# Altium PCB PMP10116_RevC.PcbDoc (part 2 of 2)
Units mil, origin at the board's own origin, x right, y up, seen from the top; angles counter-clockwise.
Board outline 9441.58 x 3500 mil, 2 copper layers (Top Layer, Bottom Layer), stack 62 mil thick; 153 components, 82 nets, 354 pads, 48 vias.
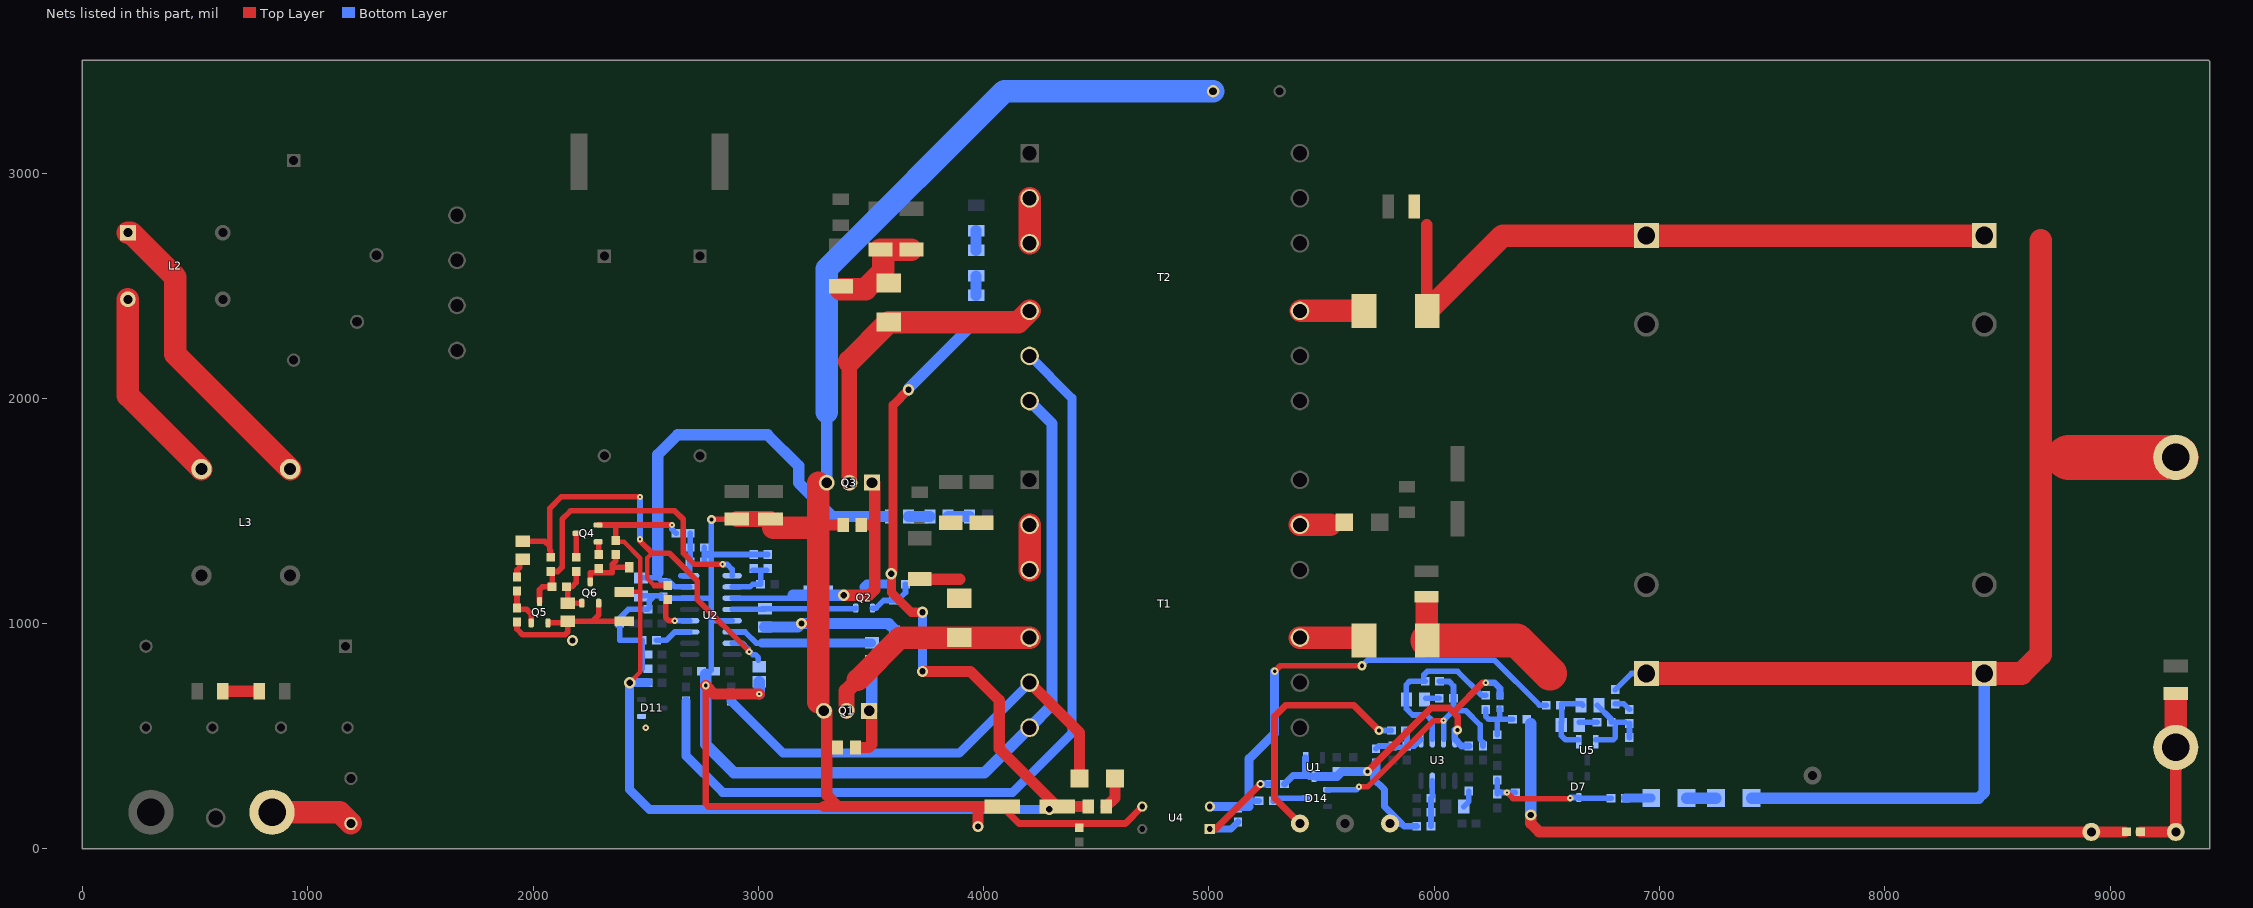
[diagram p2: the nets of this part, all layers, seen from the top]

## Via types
v1: diameter 50, hole 28, Top Layer to Bottom Layer, 21 vias
v2: diameter 28, hole 10, Top Layer to Bottom Layer, 16 vias
v3: diameter 40, hole 18, Top Layer to Bottom Layer, 8 vias
v4: diameter 34, hole 16, Top Layer to Bottom Layer, 3 vias

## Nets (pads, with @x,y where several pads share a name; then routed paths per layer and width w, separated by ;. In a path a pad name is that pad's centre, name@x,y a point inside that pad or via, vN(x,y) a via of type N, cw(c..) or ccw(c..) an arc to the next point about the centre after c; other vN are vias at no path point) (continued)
NetC26_1: C26.1 Q2.2 U2.12 | length 561.8
  Bottom Layer w25: U2.12@2884,1063.16 2939.51,1063.16 C26.1@3029.08,1063.16 ; C26.1@3016.58,1065.66 3428.91,1065.66 Q2.2@3432.05,1068.8
NetC27_2: C27.2 R35.1 | length 77.8
  Bottom Layer w25: C27.2@6131.58,188.16 6154.08,210.66 R35.1@6154.08,256.66
NetC29_1: C29.1 R34.1 R40.2 U2.8 | length 223.9
  Bottom Layer w25: U2.8@2655.55,1213.16 U2.8@2695.02,1213.16 C29.1@2695.02,1273.1 ; C29.1@2697.58,1275.66 R40.2@2697.58,1338.16 ; R40.2@2698.07,1338.65 R34.1@2698.07,1400.66
NetC30_1: C30.1 D7.3 R18.1 R38.1 R39.1 | length 614
  Top Layer w25: v2(6322.58,250.66) 6349.85,223.39 6601.81,223.39 v2(6604.08,225.66)
  Bottom Layer w25: R38.1@6279.08,244.65 C30.1@6279.08,306.66 ; R38.1@6285.08,250.66 v2(6322.58,250.66) R39.1@6360.08,250.66 ; v2(6604.08,225.66) 6606.83,228.41 D7.3@6641.58,228.41 6644.33,225.66 R18.1@6785.08,225.66
NetC31_1: C31.1 R41.1 R43.2 U2.10 | length 253.1
  Bottom Layer w25: U2.10@2884,1163.16 2963.16,1163.16 2975.66,1175.66 R41.1@3010.08,1175.66 3010.08,1235.04 ; C31.1@2975,1237.5 R43.2@3037.5,1237.5
NetC32_1: C32.1 R42.1 R45.2 U3.3 | length 204
  Bottom Layer w25: R42.1@5985.57,100.66 C32.1@5985.57,163.16 R45.2@5985.57,225.66 5991.58,231.66 U3.3@5991.58,302.14
NetC33_2: C33.2 R55.2 | length 88.9
  Top Layer w25: R55.2@1929.08,1207.15 1929.08,1238.16 1941.58,1250.66 1941.58,1273.16 C33.2@1954.08,1285.66
NetC35_1: C35.1 C42.1 D14.1 R59.2 U3.7 | length 1198.6
  Top Layer w25: v2(5666.58,275.66) 5704.08,275.66 5998.07,569.66 v2(6041.58,569.66)
  Bottom Layer w25: D14.1@5526.32,263.06 5653.98,263.06 v2(5666.58,275.66) ; C35.1@6023.07,744.66 6024.65,743.08 6066.58,743.08 6085.57,724.08 R59.2@6085.57,669.66 6085.57,613.65 ; U3.7@6041.58,487.17 v2(6041.58,569.66) ; v2@6050.83,578.91 6085.57,613.65 ; C42.1@6216.58,457.15 6216.58,473.14 6204.08,485.64 6204.08,550.66 6141.08,613.65 6085.57,613.65
NetC35_2: C35.2 C36.1 R53.2 U3.6 | length 763.9
  Bottom Layer w25: C35.2@5954.08,750.66 5954.08,773.2 5969.04,788.16 6104.08,788.16 6210.08,682.15 R53.2@6229.08,682.15 ; C35.2@5960.08,744.66 5891.58,744.66 5876.58,729.66 5876.58,622.15 5904.08,594.66 5966.26,594.66 5991.58,569.34 U3.6@5991.58,487.17
NetC36_2: C36.2 R59.1 | length 59.5
  Bottom Layer w25: C36.2@5963.07,669.66 R59.1@6022.58,669.66
NetC37_1: C37.1 R52.1 R53.1 R54.1 | length 257.7
  Bottom Layer w25: R53.1@6229.08,619.16 6229.08,588.16 6241.58,575.66 6279.08,575.66 ; C37.1@6279.08,507.15 6279.08,575.66 ; 6291.58,588.16 R52.1@6291.58,622.66 ; R54.1@6347.58,575.66 6279.08,575.66
NetC38_1: C38.1 Q6.1 R51.1 R56.1 | length 229.8
  Top Layer w25: R56.1@2148.07,1163.16 2172.68,1163.16 2191.58,1182.06 R51.1@2191.58,1231.66 ; C38.1@2154.08,1090.66 R56.1@2154.08,1157.16 ; C38.1@2154.33,1090.91 Q6.1@2216.67,1090.91
NetC39_2: C39.2 R62.1 R63.1 R66.2 U5.2 | length 334.5
  Bottom Layer w25: U5.2@6716.48,484.71 6794.13,484.71 ; C39.2@6723.07,638.16 6785.57,575.66 R63.1@6785.57,563.16 ; 6804.08,494.65 R63.1@6804.08,544.66 ; R63.1@6804.08,563.16 R62.1@6848.07,563.16 ; R66.2@6866.58,494.65 R62.1@6866.58,556.66
NetC40_1: C40.1 R63.2 | length 78.5
  Bottom Layer w25: C40.1@6644.08,563.16 R63.2@6722.58,563.16
NetC43_1: C43.1 R61.1 R64.1 R65.2 U3.5 | length 288.6
  Bottom Layer w25: R61.1@5741.58,444.65 5754.08,457.15 R65.2@5816.58,457.15 ; R65.2@5804.08,451.15 C43.1@5866.58,451.15 ; R64.1@5873.07,525.66 5879.08,519.66 C43.1@5879.08,457.15 5911.56,457.15 U3.5@5941.58,487.17
NetD1_2: D1.2 T1.9 | length 272
  Top Layer w100: T1.9@5404.08,938.16 D1.2@5676.08,938.16
NetD3_1: D3.1 R3.1 R4.1 R5.1 | length 178.1
  Top Layer w50: R5.1@3716.58,1197.61 3894.63,1197.61
NetD3_2: D3.2 Q1.2 T1.4 | length 998.4
  Top Layer w70: Q1.2@3391.58,613.16 3391.58,700.66 3441.58,750.66
  Top Layer w100: 3441.58,750.66 3629.08,938.16 T1.4@4204.08,938.16
NetD4_2: D4.2 D6.1 | length 130
  Bottom Layer w50: D6.1@7120.32,225.66 D4.2@7250.34,225.66
NetD5_2: D5.2 T1.11 | length 135
  Top Layer w100: T1.11@5404.08,1438.16 5539.12,1438.16
NetD6_2: D6.2 R18.2 | length 114.8
  Bottom Layer w40: R18.2@6848.07,225.66 D6.2@6962.84,225.66
NetD8_2: D8.2 T2.9 | length 284.5
  Top Layer w100: T2.9@5407.07,2388.16 D8.2@5691.58,2388.16
NetD9_1: D9.1 R19.1 R20.1 R22.1 | length 459.5
  Top Layer w100: R22.1@3366.58,2485.11 3476.02,2485.11 3554.08,2563.16 3554.08,2647.61 R19.1@3541.58,2660.11 R20.1@3679.08,2660.11
NetD9_2: D9.2 Q3.2 T2.4 | length 1431
  Top Layer w70: Q3.2@3404.08,1625.66 3404.08,2163.65
  Top Layer w100: 3404.08,2163.65 D9.2@3579.08,2338.65 4154.57,2338.65 T2.4@4204.08,2388.16
NetD10_1: D10.1 R28.2 | length 141
  Top Layer w50: R28.2@4544.08,188.16 4582.82,226.9 D10.1@4582.82,313.16
NetD10_2: D10.2 R24.1 T1.5 | length 2066.8
  Top Layer w50: T1.5@4204.08,738.16 4425.34,516.9 D10.2@4425.34,313.16
  Bottom Layer w40: R24.1@2879.08,656.66 3110.08,425.66 3891.58,425.66 T1.5@4204.08,738.16
NetD12_1: D12.1 Q2.1 R31.1 | length 200.7
  Bottom Layer w25: Q2.1@3506.85,1068.8 3522.21,1068.8 3556.04,1102.63 D12.1@3591.58,1102.63 ; D12.1@3604.08,1102.63 3618.54,1102.63 3653.49,1137.57 R31.1@3653.49,1175.66
NetD13_1: D13.1 Q6.3 R48.1 R49.1 | length 300.3
  Top Layer w25: Q6.3@2254.08,1185.4 2254.08,1225.66 2352.11,1225.66 2352.11,1250.66 ; R49.1@2366.58,1306.66 2366.58,1278.18 2352.11,1263.71 2352.11,1250.66 ; D13.1@2427.11,1250.66 2352.11,1250.66
NetD14_3: D14.3 R50.1 | length 151.4
  Bottom Layer w25: R50.1@5285.57,213.16 5298.07,225.66 D14.3@5431.83,225.66
NetF1_2: F1.2 TP3.1 | length 370.7
  Top Layer w100: TP3.1@841.58,163.16 1141.58,163.16 F1.2@1191.58,113.16
NetL2_1: L2.1 L3.9 | length 1354.8
  Top Layer w100: L2.1@201.87,2735.14 214.86,2735.14 412.5,2537.5 412.5,2195.57 L3.9@921.85,1686.22
NetL2_4: L2.4 L3.7 | length 888.8
  Top Layer w100: L2.4@201.87,2439.86 201.87,2012.5 L3.7@528.15,1686.22
NetQ1_1: Q1.1 R10.2 R12.2 | length 450.2
  Top Layer w50: R12.2@3431.58,450.66 3491.58,450.66 3504.08,463.16 Q1.1@3504.08,613.16
  Bottom Layer w50: Q1.1@3504.08,613.16 R10.2@3504.08,835.66
NetQ3_1: Q3.1 R32.2 R37.2 | length 743.2
  Top Layer w50: v1(3379.08,1125.66) 3479.08,1125.66 ; R37.2@3456.58,1438.16 3516.58,1438.16 ; 3491.58,1125.66 3516.58,1150.66 3516.58,1438.16 ; Q3.1@3516.58,1625.95 3516.58,1438.16
  Bottom Layer w50: R32.2@3306.58,1125.66 v1(3379.08,1125.66)
NetQ4_1: Q4.1 R48.2 | length 53.3
  Top Layer w25: R48.2@2291.58,1307.15 Q4.1@2291.58,1360.5
NetQ4_3: Q4.3 R51.2 | length 96.3
  Top Layer w25: R51.2@2191.58,1291.9 2191.58,1388.16
NetQ5_1: Q5.1 R55.1 R60.2 | length 188
  Top Layer w25: R55.1@1929.08,1144.16 R60.2@1929.08,1069.65 1935.57,1063.16 1971.97,1063.16 1991.67,1043.46 Q5.1@1991.67,1003.41
NetR1_1: R1.1 R26.2 TP2.1 TP7.1 | length 731
  Top Layer w50: R26.2@9135.57,75.66 TP7.1@9291.58,75.66 TP2.1@9291.58,450.66
  Top Layer w100: TP2.1@9291.58,450.66 9291.58,650.66
NetR2_1: R2.1 R7.2 | length 95
  Bottom Layer w50: R7.2@3842.01,1475.66 R2.1@3937.01,1475.66
NetR6_1: R6.1 R8.2 | length 160.8
  Top Layer w50: R8.2@623.66,700 R6.1@784.49,700
NetR7_1: R7.1 R9.2 | length 95
  Bottom Layer w50: R9.2@3667.01,1475.66 R7.1@3762.01,1475.66
NetR10_1: R10.1 U2.14 | length 638.3
  Bottom Layer w25: U2.14@2884,963.16 2941.58,963.16 2991.58,913.16 3016.58,913.16
  Bottom Layer w40: 3016.58,913.16 R10.1@3501.58,913.16
NetR11_1: R11.1 R17.2 | length 85.8
  Bottom Layer w50: R17.2@3966.58,2657.75 R11.1@3966.58,2743.57
NetR17_1: R17.1 R21.2 | length 85.8
  Bottom Layer w50: R21.2@3966.58,2457.75 R17.1@3966.58,2543.57
NetR26_1: R26.1 R39.2 R54.2 TP8.1 | length 3097
  Top Layer w50: v1(6429.08,150.66) 6429.08,113.16 6466.58,75.66 TP8.1@8916.58,75.66 R26.1@9066.58,75.66
  Bottom Layer w50: v1(6429.08,150.66) R54.2@6429.08,557.15
NetR27_2: R27.2 U2.3 | length 162.5
  Bottom Layer w25: R27.2@2548.07,925.66 2591.58,925.66 2629.08,963.16 U2.3@2695.02,963.16
NetR29_2: R29.2 U2.4 | length 200.8
  Top Layer w25: R29.2@2588.57,1116.15 2588.57,1027.92 2603.33,1013.16 v2(2629.08,1013.16)
  Bottom Layer w25: v2(2629.08,1013.16) U2.4@2695.02,1013.16
NetR32_1: R32.1 U2.11 | length 382.6
  Bottom Layer w25: U2.11@2884,1113.16 3191.58,1113.16
  Bottom Layer w50: 3154.08,1125.66 R32.1@3229.08,1125.66
NetR44_2: R44.2 R46.2 U4.1 | length 489.2
  Top Layer w30: U4.1@5004.08,88.16 5029.08,88.16 v4(5229.08,288.16)
  Bottom Layer w30: U4.1@5004.08,88.16 5098.07,88.16 R46.2@5129.08,119.16 ; v4(5229.08,288.16) R44.2@5272.58,288.16
NetR46_1: R46.1 R50.2 R57.1 U4.2 | length 2162.8
  Top Layer w25: v4(5291.58,788.16) 5316.58,813.16 v3(5679.08,813.16)
  Bottom Layer w25: 5178.83,213.16 R50.2@5222.58,213.16 ; v3(5679.08,813.16) 5704.08,838.16 6266.58,838.16 6466.58,638.16 R57.1@6497.58,638.16
  Bottom Layer w40: U4.2@5004.08,188.16 R46.1@5123.07,188.16 ; R46.1@5135.08,188.16 5178.83,188.16 5178.83,213.16 5178.83,400.41 5291.58,513.16 v4(5291.58,788.16)
NetR58_2: R58.2 R62.2 | length 72.7
  Bottom Layer w25: R58.2@6804.08,644.16 6842.07,644.16 R62.2@6866.58,619.65
NetR64_2: R64.2 TP10.1 | length 1107.4
  Top Layer w30: TP10.1@5404.08,113.16 5291.58,225.66 5291.58,588.16 5341.58,638.16 5641.58,638.16 v3(5754.08,525.66)
  Bottom Layer w25: v3(5754.08,525.66) R64.2@5810.08,525.66
NetT1_2: T1.2 T1.3 | length 200
  Top Layer w100: T1.3@4204.08,1238.16 T1.2@4204.08,1438.16
NetT2_2: T2.2 T2.3 | length 200
  Top Layer w100: T2.3@4204.08,2688.16 T2.2@4204.08,2888.16
OPTO_SEC: C39.1 C40.2 R57.2 U5.1 | length 319.7
  Bottom Layer w25: C40.2@6564.08,563.16 6564.08,503.16 6582.52,484.71 U5.1@6641.67,484.71 ; C40.2@6566.58,565.66 6566.58,644.16 6654.08,644.16 C39.1@6660.08,638.16
PGND: C11.2 C16.2 C17.1 C18.2 C22.2 C24.2 C26.2 C28.2 C29.2 C31.2 C34.2 C38.2 C41.1 D11.1 D12.2 Q1.3 Q3.3 Q5.2 Q6.2 R12.1 R14.1 R15.1 R16.1 R27.1 R30.1 R33.1 R36.1 R37.1 R40.1 R43.1 R60.1 T1.6 T2.6 U2.6 U2.13 U4.3 | length 14728.6
  Top Layer w25: R60.1@1929.08,1006.66 1929.08,975.66 1954.08,950.66 2141.58,950.66 2154.08,963.16 C38.2@2154.08,1010.66 ; Q5.2@2066.48,1003.41 2146.83,1003.41 C38.2@2154.08,1010.66 ; 2279.04,1023.2 2277.83,1024.41 ; Q6.2@2291.58,1090.82 2291.58,1038.16 2277.83,1024.41 ; C18.2@2416.58,1010.7 2416.54,1010.66 2264.08,1010.66 ; v3(2791.58,1463.16) R14.1@2902.6,1463.16 ; C38.2@2154.08,1010.66 2264.08,1010.66 ; 2264.08,1010.66 2277.83,1024.41
  Top Layer w30: v4(2766.58,725.66) 2766.58,200.66 2779.08,188.16 3291.58,188.16 ; C28.2@4082.03,188.16 4157.03,113.16 4629.08,113.16 U4.3@4704.08,188.16
  Top Layer w40: v1(3191.58,1000.66) 3266.58,1000.66
  Top Layer w50: v4(2766.58,725.66) 2804.08,688.16 v2(3004.08,688.16) ; 3266.58,650.66 3304.08,613.16 3304.08,238.16 3354.08,188.16 ; 3266.58,1625.66 Q3.3@3279.08,1638.16 ; 3291.58,188.16 3354.08,188.16 ; 3304.08,1438.16 R37.1@3376.58,1438.16 ; v1(3975,100) 3975,188.16 ; C28.2@4082.03,188.16 3975,188.16 ; 3354.08,188.16 3975,188.16
  Top Layer w70: R14.1@2904.08,1464.64 R15.1@3054.08,1464.64
  Top Layer w100: 3066.58,1425.66 3243.05,1425.66 ; 3266.58,650.66 3266.58,1000.66 3266.58,1625.66
  Bottom Layer w25: R16.1@2479.08,1123.16 C11.2@2569.08,1123.16 ; 2485.08,800.66 2485.08,863.16 R27.1@2485.08,925.66 2385.08,925.66 R36.1@2385.08,1000.66 2385.08,1025.66 2422.58,1063.16 R33.1@2510.08,1063.16 2516.58,1069.66 2516.58,1100.66 2529.08,1113.16 ; C11.2@2569.08,1113.16 U2.6@2695.02,1113.16 2779.08,1113.16 2791.58,1100.66 ; C29.2@2760.57,1275.66 R40.1@2760.57,1338.16 ; 2760.82,1307.16 2791.58,1307.16 ; 2772.58,775.66 2791.58,794.66 2791.58,1013.16 ; v3(2791.58,1463.16) 2791.58,1307.16 ; U2.13@2884,1013.16 2791.58,1013.16 ; R43.1@3041.58,1307.16 2791.58,1307.16 ; 2791.58,1013.16 2791.58,1100.66 ; 2791.58,1100.66 2791.58,1307.16
  Bottom Layer w50: C16.2@2766.58,775.66 v4(2766.58,725.66) 2766.58,463.16 2891.58,338.16 4004.08,338.16 T1.6@4204.08,538.16 4304.08,638.16 4304.08,1888.16 T2.6@4204.08,1988.16 ; v2(3004.08,688.16) C22.2@3004.08,742.19 ; C26.2@3029.08,985.66 3176.58,985.66 v1(3191.58,1000.66) 3579.08,1000.66 3579.08,998.69 D12.2@3604.08,973.69 ; Q3.3@3304.08,1638.16 3304.08,1938.16
  Bottom Layer w100: 3304.08,1938.16 3304.08,2575.66 4091.58,3363.16 C41.1@5018.94,3363.16
  other v1: 2175,925
  other v2: 2500,537.5
SD: Q5.3 R47.1 R56.2 U2.9 | length 1449
  Top Layer w25: Q5.3@2029.08,1097.9 2029.08,1150.66 2041.58,1163.16 R56.2@2085.08,1163.16 2085.08,1225.66 R47.1@2079.08,1231.66 2110.08,1231.66 2129.08,1250.66 2129.08,1463.16 2166.58,1500.66 2629.08,1500.66 2666.58,1463.16 2666.58,1313.16 2716.58,1263.16 v2(2841.58,1263.16)
  Bottom Layer w25: v2(2841.58,1263.16) 2842.23,1262.5 2862.5,1262.5 2884,1241 U2.9@2884,1213.16
VCC: C18.1 C28.1 Q2.3 Q4.2 R21.1 R25.2 R28.1 R31.2 R34.2 R49.2 | length 6720.3
  Top Layer w20: R49.2@2373.07,1363.16 2404.08,1363.16 2476.62,1290.62 2476.62,1140.62 ; C18.1@2404.08,1140.62 2476.62,1140.62 ; v1(2429.08,738.16) 2476.62,785.7 2476.62,1140.62
  Top Layer w25: Q4.2@2288.82,1438.06 2362.5,1438.06 ; R49.2@2366.58,1369.65 2366.58,1433.98 2362.5,1438.06 ; v2(2616.58,1438.16) 2616.48,1438.06 2362.5,1438.06
  Top Layer w40: v1(3666.58,2038.16) 3598.05,1969.64 3598.05,1228.61 v1(3590.49,1221.05) 3590.49,1139.24 3679.08,1050.66 v1(3729.08,1050.66)
  Top Layer w50: v1(3729.08,788.16) 3941.58,788.16 4069.04,660.7 4069.04,445.25 C28.1@4326.12,188.16 4429.08,188.16
  Bottom Layer w25: v2(2616.58,1438.16) 2616.58,1419.16 R34.2@2635.08,1400.66
  Bottom Layer w40: R25.2@2510.08,738.16 v1(2429.08,738.16) 2429.08,263.16 2516.58,175.66 v1(4291.58,175.66) ; Q2.3@3469.45,1163.29 3481.82,1175.66 R31.2@3590.49,1175.66 v1(3590.49,1221.05) ; v1(3729.08,788.16) v1(3729.08,1050.66)
  Bottom Layer w50: v1(3666.58,2038.16) 3666.58,2043.57 R21.1@3966.58,2343.57
VINAC: C11.1 R9.1 R16.2 U2.7 | length 2021.8
  Bottom Layer w25: R16.2@2479.08,1203.16 2554.08,1203.16 ; 2558.07,1203.16 C11.1@2579.08,1182.16 2585.08,1188.16 2604.08,1188.16 2629.08,1163.16 U2.7@2695.02,1163.16
  Bottom Layer w50: 2554.08,1225.66 2554.08,1750.66 2641.58,1838.16 3041.58,1838.16 3179.08,1700.66 3179.08,1625.66 3329.08,1475.66 R9.1@3587.01,1475.66
VOUT: C1.1 C2.1 C3.1 C19.1 C20.1 C21.1 D1.1 D4.1 D8.1 R58.1 TP1.1 | length 9590
  Top Layer w50: D8.1@5966.58,2391.15 5966.58,2770.25
  Top Layer w100: 5966.58,1083.14 5966.58,928.65 D1.1@5969.57,925.66 ; D8.1@5969.57,2388.16 6304.08,2722.67 6941.42,2722.67 C20.1@6941.58,2722.51 C21.1@8441.58,2722.51 ; C2.1@6941.58,778.81 C3.1@8441.58,778.81 8607.23,778.81 8691.58,863.16 8691.58,2700.66
  Top Layer w150: D1.1@5969.57,925.66 6366.58,925.66 6513.43,778.81
  Top Layer w200: 8816.58,1738.16 TP1.1@9291.58,1738.16
  Bottom Layer w25: R58.1@6804.08,707.16 6875.73,778.81 C2.1@6941.58,778.81
  Bottom Layer w50: D4.1@7407.82,225.66 8416.58,225.66 8441.58,250.66 C3.1@8441.58,778.81
VREF: C22.1 C33.1 R29.1 R47.2 U2.15 | length 2089.3
  Top Layer w20: 2529.08,1313.16 2507.62,1291.7 2507.62,1200.66 2538.62,1169.66
  Top Layer w25: C33.1@1954.08,1365.66 2051.58,1365.66 2075,1342.23 ; R47.2@2079.08,1294.65 2079.08,1323.14 2075,1327.22 2075,1342.23 ; v2(2475,1375) 2475,1367.23 2529.08,1313.16 2604.68,1313.16 2729.68,1188.16 2729.68,1106.16 v2(2960.18,875.66) ; v2(2475,1562.5) 2125,1562.5 2075,1512.5 2075,1342.23 ; 2538.62,1169.66 R29.1@2597.78,1169.66
  Bottom Layer w25: v2(2475,1375) v2(2475,1562.5) ; U2.15@2884,913.16 2929.08,913.16 2954.08,888.16 2954.08,875.66 v2(2960.18,875.66) 2961.84,875.66 2975,862.5 2987.5,862.5 3000,850 3000,837.5
VREF_SEC: C15.1 C44.2 R13.1 R42.2 R44.1 R52.2 R61.2 TP6.1 U1.1 U1.3 U3.8 | length 1927.3
  Top Layer w30: v3(5704.08,344.16) 5985.57,625.66 6066.58,625.66 6085.33,606.91 ; v3(6104.08,528.51) 6104.08,588.16 6085.33,606.91 ; v2(6229.08,738.16) 6216.58,738.16 6085.33,606.91
  Bottom Layer w30: R44.1@5335.57,288.16 5372.97,325.56 5441.67,325.56 5445.41,321.82 5479.08,321.82 ; 5429.08,325.66 U1.1@5429.08,404.6 ; 5732.53,344.16 5729.08,340.71 5729.08,313.16 5779.08,263.16 5779.08,188.16 5854.08,113.16 ; TP6.1@5841.58,113.16 5854.08,113.16 ; R42.2@5922.58,100.66 5866.58,100.66 5854.08,113.16 ; v3@6091.58,528.51 U3.8@6091.58,487.17 6121.6,457.15 C44.2@6154.08,457.15 ; v2(6229.08,738.16) 6266.58,738.16 6291.58,713.16 R52.2@6291.58,678.66
  Bottom Layer w40: 5479.08,321.82 5569.23,321.82 5591.58,344.16 R13.1@5641.58,344.16 v3(5704.08,344.16) 5732.53,344.16 5741.54,353.18 R61.2@5741.54,381.63
ZCDB: R23.1 T2.5 | length 3884.7
  Bottom Layer w40: R23.1@2679.08,656.66 2679.08,413.16 2841.58,250.66 4129.08,250.66 4391.58,513.16 4391.58,2000.66 T2.5@4204.08,2188.16
pads on no net: D7.2 D11.2 T1.7 T1.8 T2.7 T2.8 T2.10 T2.11

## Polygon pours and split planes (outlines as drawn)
NetC4_1 on Top Layer "Top Layer-No Net" (solid, remove dead copper, pour order 19): 2779.08,3312.5 4291.58,3312.5 4291.58,2975.66 2779.08,2975.66
NetC4_1 on Top Layer "Top Layer-No Net 1" (solid, remove dead copper, pour order 20): 3316.58,3013.16 3316.58,2854.4 3320.32,2850.66 3766.58,2850.66 3766.58,3000.66 3754.08,3013.16
NetD9_1 on Top Layer "Top Layer-No Net 2" (solid, remove dead copper, pour order 21): 3309.49,2538.16 3579.08,2538.16 3579.08,2688.16 3591.58,2675.66 3779.08,2675.66 3779.08,2425.66 3304.08,2425.66
NetC4_1 on Top Layer "Top Layer-No Net 4" (solid, remove dead copper, pour order 22): 3666.58,1525.66 4069.04,1525.66 4069.04,1912.5 3666.58,1912.5
NetD3_1 on Top Layer "Top Layer-No Net 5" (solid, remove dead copper, pour order 23): 3816.58,1475.66 3816.58,1150.66 4029.08,1150.66 4029.08,1475.66
NetC6_1 on Top Layer "Top Layer-No Net 7" (solid, remove dead copper, pour order 27): 2354.08,2588.16 1941.58,2588.16 1941.58,3225.66 2241.58,3225.66 2241.58,2913.16
GND on Top Layer "Top Layer-No Net 8" (solid, remove dead copper, pour order 30): 6416.58,1075.66 8541.58,1075.66 8541.58,2425.66 6416.58,2425.66
VOUT on Top Layer "Top Layer-No Net 9" (solid, remove dead copper, pour order 31): 6279.08,2688.16 8954.08,2688.16 8954.08,3150.66 6279.08,3150.66
VOUT on Top Layer "Top Layer-No Net 10" (solid, remove dead copper, pour order 32): 5916.58,3150.66 5916.58,2450.66 6016.58,2450.66 6054.08,2450.66 6329.08,2725.66 6341.58,2738.16 6341.58,3150.66
VOUT on Top Layer "Top Layer-No Net 12" (solid, remove dead copper, pour order 33): 8641.58,3025.66 8954.08,3025.66 8954.08,525.66 8641.58,525.66
GND on Top Layer "Top Layer-No Net 13" (solid, remove dead copper, pour order 34): 5539.12,3138.16 5539.12,2625.66 5551.62,2638.16 5804.08,2638.16 5804.08,3138.16
VOUT on Top Layer "Top Layer-No Net 11" (solid, remove dead copper, pour order 35): 6066.58,850.66 6566.58,350.66 6666.58,350.66 8954.08,350.66 8954.08,850.66
GND on Top Layer "Top Layer-No Net 15" (solid, remove dead copper, pour order 36): 9391.58,0.66 9054.08,0.66 9054.08,1563.16 9391.58,1563.16
CS on Top Layer "Top Layer-No Net 3" (solid, remove dead copper, pour order 24): 3091.58,1575.66 2791.58,1575.66 2791.58,1588.16 2579.08,1800.66 2579.08,1825.66 3091.58,1825.66
PGND on Top Layer "Top Layer-No Net 6" (solid, remove dead copper, pour order 25): 3341.58,163.16 1825,163.16 1825,1475.66 3341.58,1475.66
GND on Top Layer "Top Layer-No Net 14" (solid, remove dead copper, pour order 28): 5454.08,13.16 5454.08,700.66 6141.58,700.66 6554.08,288.16 6566.58,288.16 9416.58,288.16 9416.58,0.66 5454.08,0.66
GND on Bottom Layer "Bottom Layer-No Net" (solid, remove dead copper, pour order 26): 5379.08,3463.16 5379.08,13.16 9416.58,13.16 9416.58,3463.16
PGND on Bottom Layer "Bottom Layer-No Net 1" (solid, remove dead copper, pour order 29): 1825,2025.66 4279.08,2025.66 4291.58,2013.16 4291.58,20.84 2146.4,20.84 1825,342.23

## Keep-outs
Keep-Out Layer:
  text ".Layer_Name" at 577,-858.49 h60

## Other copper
Top Layer:
  pour cut-out: 3054.08,475.66 3054.08,863.16 3091.58,863.16 3091.58,475.66
  text ".Layer_Name" at 577,-858.49 h60
Bottom Layer:
  text ".Layer_Name" at 577,-858.49 h60

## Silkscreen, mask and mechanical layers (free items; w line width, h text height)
Top Overlay:
  text "Vout" at 9000,1725 h30
  text "Warning!" at 9091.58,1563.16 h30
  text "High" at 9091.58,1500.66 h30
  text "Voltage!" at 9091.58,1425.66 h30
  text "GND" at 9237.5,1062.5 h30
  text "PMP10116_RevC" at 1462.5,150 h60
  text "VDIM" at 5350,12.5 h30
  text "GND" at 5562.5,12.5 h30
  text ".Layer_Name" at 577,-858.49 h30
Bottom Overlay:
  text ".Layer_Name" at 577,-858.49 h30
Top Paste:
  text ".Layer_Name" at 577,-858.49 h60
Bottom Paste:
  text ".Layer_Name" at 577,-858.49 h60
Top Solder:
  text ".Layer_Name" at 577,-858.49 h60
  text ".Layer_Name" at 577,-858.49 h60
Bottom Solder:
  text ".Layer_Name" at 577,-858.49 h60
Drill Guide:
  text ".Layer_Name" at 577,-858.49 h60
M1 Board Outline:
  the board outline again, w10
  text ".Layer_Name" at 577,-858.49 h60
M2 Board Dimensions:
  text ".Layer_Name" at 577,-858.49 h60
M3 3D STEP Top:
  text ".Layer_Name" at 577,-858.49 h60
M4 3D STEP Bottom:
  text ".Layer_Name" at 577,-858.49 h60
M5 Assembly Top:
  lines w10: -292,-930.17 6308,-930.17 ; -292,-726.83 6310,-726.83 ; -292,-523.5 -292,-1133.5 3713,-1133.5 6310,-1133.5 6310,-523.5 -291.5,-523.5 -291.5,-1133.5 1284,-1133.5 ; 2173,-1133.5 2173,-523.5 ; 3440,-726.83 3440,-523.5 ; 4280,-726.83 4280,-523.5 ; 4902,-1140 4902,-937.17
  text "PCB VIEWED FROM TOP SIDE" at -228.5,-655.67 h60
  text "BOARD #:" at 2248,-655.67 h60
  text ".PRJ_Number" at 2793.5,-655.67 h60
  text "REV:" at 3638,-655.67 h60
  text ".PCB_Rev" at 3929.5,-655.67 h60
  text "SVN REV:" at 4476,-655.67 h60
  text ".VersionControl_RevNumber" at 4982,-655.67 h60
  text "PLOT NAME =" at -228.5,-1064.34 h60
  text ".plot_File_Name" at 577,-1064.34 h60
  text "GENERATED    :" at 2250,-1064.34 h60
  text ".Print_Date" at 3119.5,-1064.34 h60
  text ".Print_Time" at 3848.5,-1064.34 h60
  text "TEXAS INSTRUMENTS" at 5113,-1064.34 h60
M6 Assembly Bottom:
  lines w10: -292.5,-727.33 6309.5,-727.33 ; -290.5,-930.67 6309.5,-930.67 ; 1115.5,-1140.5 1115.5,-937.67 ; 1737.5,-727.33 1737.5,-524 ; 2577.5,-727.33 2577.5,-524 ; 3844.5,-1134 3844.5,-524 ; 4733.5,-1134 6309,-1134 6309,-524 -292.5,-524 -292.5,-1134 2304.5,-1134 6309.5,-1134 6309.5,-524
  text ".VersionControl_RevNumber" at 1035.5,-656.17 h60
  text "SVN REV:" at 1541.5,-656.17 h60
  text ".PCB_Rev" at 2088,-656.17 h60
  text "REV:" at 2379.5,-656.17 h60
  text ".PRJ_Number" at 3224,-656.17 h60
  text "BOARD #:" at 3769.5,-656.17 h60
  text "PCB VIEWED FROM BOTTOM SIDE" at 6246,-656.17 h60
  text "TEXAS INSTRUMENTS" at 904.5,-1064.84 h60
  text ".Print_Time" at 2169,-1064.84 h60
  text ".Print_Date" at 2898,-1064.84 h60
  text "GENERATED    :" at 3767.5,-1064.84 h60
  text ".plot_File_Name" at 5440.5,-1064.84 h60
  text "PLOT NAME =" at 6246,-1064.84 h60
M9 Title Sheet:
  drawing of 57 lines, arcs and shapes, not listed
  text "1" at 739.84,8036.5 h70
  text "2" at 3235.5,8036.5 h70
  text "3" at 5724.84,8036.5 h70
  text "4" at 8231.51,8036.5 h70
  text "5" at 10730.5,8036.5 h70
  text "6" at 13235.5,8036.5 h70
  text "A" at -416.5,6893.5 h70
  text "A" at 14383.5,6893.5 h70
  text "B" at -416.5,4513.5 h70
  text "B" at 14383.5,4513.5 h70
  text "C" at -416.5,2138.5 h70
  text "C" at 14383.5,2138.5 h70
  text "PROJECT TITLE:" at 11343.5,277.5 h45
  text ".PRJ_Title" at 11393.5,144.17 h70
  text "DESIGNED FOR:" at 11343.5,-23.5 h45
  text ".PRJ_Customer" at 11393.5,-163.5 h70
  text "D" at -416.5,-231.5 h70
  text "D" at 14383.5,-231.5 h70
  text "FILE NAME:" at 11343.5,-323.5 h45
  text ".PCB_File_Name_No_Path" at 11393.5,-443.5 h70
  text "Texas Instruments (TI) and/or its licensors do not warrant the accuracy or completeness of this specification" at 6374,-605.34 h45
  text "ENGINEER:" at 11343.5,-613.5 h45
  text "LAYOUT BY:" at 12848.5,-613.5 h45
  text "or any information contained therein. TI and/or its licensors do not warrant that this design will meet" at 6329.01,-718 h45
  text ".PRJ_Engineer" at 11393.5,-768.49 h70
  text ".PCB_Layout" at 12899,-768.49 h70
  text "the specifications, will be suitable for your application or fit for any particular purpose, or will operate in" at 6329.01,-830.67 h45
  text ".Layer_Name" at 577,-858.49 h60
  text "ALTIUM DESIGNER VERSION:" at 12848.5,-923.5 h45
  text "an implementation. TI and/or its licensors do not warrant that the design is production worthy. You should" at 6329.01,-943.33 h45
  text "completely validate and test your design implementation to confirm the system functionality for your application." at 6374,-1056 h45
  text ".print_Scale" at 11393.5,-1056.83 h70
  text ".Application_BuildNumber" at 12899,-1056.83 h70
  text "1" at 739.84,-1263.5 h70
  text "2" at 3235.5,-1263.5 h70
  text "3" at 5724.84,-1263.5 h70
  text "4" at 8231.51,-1263.5 h70
  text "5" at 10730.5,-1263.5 h70
  text "6" at 13235.5,-1263.5 h70
M10 Fab Notes:
  drawing of 185 lines, arcs and shapes, not listed
  text "DESIGN INFORMATION" at 12381.02,5910 h60
  text "MIN. TRACK WIDTH:" at 11736.46,5730 h60
  text "8" at 12832.7,5730 h60
  text "MIL" at 12987.46,5730 h60
  text "MIN. CLEARANCE:" at 11736.46,5598 h60
  text "0.2" at 12772.7,5598 h60
  text "mm" at 12987.46,5598 h60
  text "MIN. VIA PAD SIZE:" at 11736.46,5466 h60
  text "24" at 12802.71,5466 h60
  text "MIL" at 12987.46,5466 h60
  text "0.05mm (2MIL)" at 12431.46,5324.29 h60
  text "MINIMUM ANNULAR RING" at 11407.23,5320 h60
  text "EXTERNAL" at 13139.46,5320 h60
  text "PER" at 11607.23,5202 h60
  text "IPC-D-275 CLASS 2 LEVEL C" at 11827.23,5202 h60
  text "MIL, HOLES" at 13315.46,5089.71 h60
  text "+/-" at 12923,5089 h60
  text "+/-" at 13777,5089 h60
  text "REGISTRATION TOLERANCES:" at 11407.23,5084 h60
  text "METAL" at 12607,5084 h60
  text "5" at 13183.2,5084 h60
  text "3" at 14016.2,5084 h60
  text "MIL" at 14132.46,5084 h60
  text "MATERIAL:" at 11332.46,4874.54 h60
  text "FR-4 High Tg" at 12318.9,4734.21 h60
  text "FR-408" at 11753.46,4725.64 h60
  text "X" at 12165.46,4725.64 h60
  text "OTHER" at 13241.46,4725.64 h60
  text "62 MIL (1.6mm) +/-10%" at 12073.56,4562.92 h60
  text "THICKNESS:" at 11407.23,4558.64 h60
  text "X" at 11945.4,4558.64 h60
  text "OTHER" at 13358.46,4558.64 h60
  text "TOLERANCE:" at 11407.23,4400.64 h60
  text "X" at 12246.53,4400.64 h60
  text "ANSI IPC-6012 TYPE 3 CLASS 2" at 12433.48,4400.64 h60
  text "OTHER +/-" at 12433.46,4244.64 h60
  text "BOW & TWIST:" at 11407.23,4087.64 h60
  text "X" at 12246.53,4087.64 h60
  text "ANSI IPC-6012 TYPE 3 CLASS 2" at 12433.48,4087.64 h60
  text "OTHER +/-" at 12433.46,3929.13 h60
  text "DRILLING:" at 11332.46,3790.64 h60
  text "REFERENCE:" at 11407.23,3673.64 h60
  text "X" at 12055.46,3673.64 h60
  text "AS SHOWN" at 12242.46,3673.64 h60
  text "X" at 12956.46,3673.64 h60
  text "NC_DRILL FILES" at 13093.46,3673.64 h60
  text "PTH MIN COPPER THICKNESS:" at 11407.23,3515.64 h60
  text "X" at 12757.46,3515.64 h60
  text "1MIL" at 12894.46,3515.64 h60
  text "OTHER" at 13391.46,3515.64 h60
  text "BOARD FINISH:" at 11332.46,3356.64 h60
  text "SILKSCREEN:" at 11487.68,3238.64 h60
  text "X" at 12436.46,3238.64 h60
  text "TOP" at 12562.46,3238.64 h60
  text "X" at 12946.46,3238.64 h60
  text "BOTTOM" at 13073.46,3238.64 h60
  text "SILKSCREEN COLOR:" at 11487.68,3071.64 h60
  text "X" at 12435.42,3071.64 h60
  text "WHITE" at 12562.46,3071.64 h60
  text "OTHER" at 13073.46,3071.64 h60
  text "SOLDER RESIST COLOR:" at 11487.68,2901.64 h60
  text "X" at 12055.42,2742.44 h60
  text "GREEN" at 12182.46,2742.44 h60
  text "BLUE" at 12773.46,2742.44 h60
  text "OTHER" at 13311.46,2742.44 h60
  text "IMMERSION GOLD (ENIG)" at 12393.46,2553.92 h60
  text "ENEPIG" at 13731,2550.64 h60
  text "SURFACE FINISH:" at 11332.46,2549.64 h60
  text "X" at 12206.51,2549.64 h60
  text "IMM. TIN/SILVER OR EQUIV" at 11662,2392.64 h60
  text "OTHER" at 13093.46,2392.64 h60
  text "ARRAY/PANEL:" at 11332.46,2213.64 h60
  text "CUT AND TRIM PER MECH LAYER 1" at 12393.46,2209.35 h60
  text "N.C. ROUTE" at 12393.46,2057.64 h60
  text "X" at 13072.46,2057.64 h60
  text "V. SCORE" at 13259.46,2057.64 h60
  text "CERTIFICATION:" at 11332.46,1920.64 h60
  text "MATERIALS AND WORKMANSHIP FOR ALL PCBS" at 12057.46,1920.64 h60
  text "TO MEET OR EXCEED THE REQUIREMENTS OF:" at 12057.46,1822.64 h60
  text "X" at 11683.96,1686.13 h60
  text "ANSI IPC-A-600F CLASS ->" at 11822.96,1686.13 h60
  text "X" at 13462.02,1686.13 h60
  text "2" at 13580.96,1686.14 h60
  text "1" at 13265.96,1684.64 h60
  text "3" at 13934.96,1684.64 h60
  text "X" at 11686.02,1526.64 h60
  text "UL 94V-0" at 11822.96,1526.64 h60
  text "X" at 12498.02,1526.64 h60
  text "RoHS" at 12634.96,1526.64 h60
  text "OTHER" at 13279.36,1526.64 h60
  text "PER ORDER" at 13676.42,1526.64 h60
  text "ADDITIONAL REQUIREMENTS:" at 11332.46,1385.64 h60
  text "MICROSECTION:" at 11407.23,1270.64 h60
  text "YES" at 12312.96,1270.64 h60
  text "REQUIRED" at 13174.46,1114.49 h60
  text "BARE BOARD ELEC. TEST:" at 11407.23,1111.64 h60
  text "NONE" at 12712.96,1111.64 h60
  text "X" at 13047.46,1111.64 h60
  text "PER ORDER" at 13766.46,1111.64 h60
  text "MANUFACTURER'S UL:" at 11407.23,954.64 h60
  text "RAIL" at 12572.96,950.35 h60
  text "METAL" at 13064.77,950.35 h60
  text "X" at 13440,950 h60
  text "SILK" at 13576.46,950.35 h60
  text ".Layer_Name" at 577,-858.49 h60
M11 Gerber Information:
  lines w10: -292,-930.17 6308,-930.17 ; -292,-726.83 6310,-726.83 ; -292,-523.5 -292,-1133.5 3713,-1133.5 6310,-1133.5 6310,-523.5 -291.5,-523.5 -291.5,-1133.5 1284,-1133.5 ; 2173,-1133.5 2173,-523.5 ; 3440,-726.83 3440,-523.5 ; 4280,-726.83 4280,-523.5 ; 4902,-1140 4902,-937.17
  text "ALL ARTWORK VIEWED FROM TOP SIDE" at -228.5,-655.67 h60
  text "BOARD #:" at 2248,-655.67 h60
  text ".PRJ_Number" at 2793.5,-655.67 h60
  text "REV:" at 3638,-655.67 h60
  text ".PCB_Rev" at 3929.5,-655.67 h60
  text "SVN REV:" at 4476,-655.67 h60
  text ".VersionControl_RevNumber" at 4982,-655.67 h60
  text "LAYER NAME =" at -228.5,-858.49 h60
  text "PLOT NAME =" at -228.5,-1064.34 h60
  text ".plot_File_Name" at 577,-1064.34 h60
  text "GENERATED    :" at 2250,-1064.34 h60
  text ".Print_Date" at 3119.5,-1064.34 h60
  text ".Print_Time" at 3848.5,-1064.34 h60
  text "TEXAS INSTRUMENTS" at 5113,-1064.34 h60
M12 Stackup:
  drawing of 191 lines, arcs and shapes, not listed
  text "Layer" at 9790.58,7830 h60
  text "Name" at 10200.49,7830 h60
  text "Material" at 11130.23,7830 h60
  text "Thickness" at 11990,7830 h60
  text "Constant" at 12639.84,7830 h60
  text "Board Layer Stack" at 13209.7,7830 h60
  text "1" at 9790.58,7710 h60
  text "Top Overlay" at 10200.49,7710 h60
  text "2" at 9790.58,7590 h60
  text "Top Solder" at 10200.49,7590 h60
  text "Solder Resist" at 11130.23,7590 h60
  text "0.40mil" at 11990,7590 h60
  text "3.5" at 12639.84,7590 h60
  text "3" at 9790.58,7470 h60
  text "Top Layer" at 10200.49,7470 h60
  text "Copper" at 11130.23,7470 h60
  text "1.40mil" at 11990,7470 h60
  text "4" at 9790.58,7350 h60
  text "Dielectric1" at 10200.49,7350 h60
  text "FR-4" at 11130.23,7350 h60
  text "59.20mil" at 11990,7350 h60
  text "4.8" at 12639.84,7350 h60
  text "5" at 9790.58,7230 h60
  text "Bottom Layer" at 10200.49,7230 h60
  text "Copper" at 11130.23,7230 h60
  text "1.40mil" at 11990,7230 h60
  text "6" at 9790.58,7110 h60
  text "Bottom Solder" at 10200.49,7110 h60
  text "Solder Resist" at 11130.23,7110 h60
  text "0.40mil" at 11990,7110 h60
  text "3.5" at 12639.84,7110 h60
  text "7" at 9790.58,6990 h60
  text "Bottom Overlay" at 10200.49,6990 h60
  text ".Layer_Name" at 577,-858.49 h60
M13 Component Bodies Top:
  text ".Layer_Name" at 577,-858.49 h60
M14 Component Bodies Bottom:
  text ".Layer_Name" at 577,-858.49 h60
M15 Courtyards Top:
  text ".Layer_Name" at 577,-858.49 h60
M16 Courtyards Bottom:
  text ".Layer_Name" at 577,-858.49 h60
Drill Drawing:
  text ".Layer_Name" at 577,-858.49 h60

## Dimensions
0,0 to 9441.58,0 on M2 Board Dimensions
